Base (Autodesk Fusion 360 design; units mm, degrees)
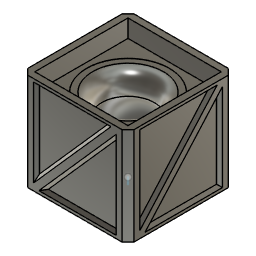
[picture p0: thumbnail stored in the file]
base_feature "Base Feature"
sketch "Sketch1" plane through (0, 0, 16.5) normal (0, 0, 1) x axis (-1, 0, 0)
  line L1 (-9, -9) -> (9, -9)
  line L2 (-9, 9) -> (-9, -9)
  line L3 (9, 9) -> (-9, 9)
  line L4 (9, -9) -> (9, 9)
  line L5 (-7, -7) -> (7, -7)
  line L6 (-7, 7) -> (-7, -7)
  line L7 (7, 7) -> (-7, 7)
  line L8 (7, -7) -> (7, 7)
  circle C1 centre (0, 0) radius 9
  circle C2 centre (0, 0) radius 7
  circle C3 centre (0, 0) radius 9
  horizontal L1
  vertical L2
  horizontal L3
  vertical L4
  horizontal L5
  vertical L6
  horizontal L7
  vertical L8
  concentric C1 C3
  tangent L1 C3
sketch "Sketch2" plane through (-9, 0, 0) normal (-1, 0, 0) x axis (0, -1, 0)
  line L1 (-9, 16.5) -> (9, 16.5)
  line L2 (-9, 0) -> (-9, 16.5)
  line L3 (9, 0) -> (-9, 0)
  line L4 (9, 16.5) -> (9, 0)
  line L5 (6.5, 1) -> (-6.5, 1)
  line L6 (-6.5, 15.5) -> (6.5, 15.5)
  line L7 (-6.5, 1) -> (-6.5, 15.5)
  line L8 (6.5, 15.5) -> (6.5, 1)
  line L9 (6.5, 14) -> (-5, 1)
  line L10 (-6.5, 2.5) -> (5, 15.5)
  point P8 (-6.5, 2.5)
  point P9 (-5, 1)
  point P13 (6.5, 14)
  point P7 (5, 15.5)
  horizontal L5
  vertical L8
  horizontal L6
  vertical L7
  coincident P8 L7
  coincident P9 L5
  coincident P13 L8
  coincident P7 L6
sketch "Sketch3" plane through (0, 9, 0) normal (0, 1, 0) x axis (-1, 0, 0)
  line L1 (-9, 16.5) -> (9, 16.5)
  line L2 (-9, 0) -> (-9, 16.5)
  line L3 (9, 0) -> (-9, 0)
  line L4 (9, 16.5) -> (9, 0)
  line L5 (6.5, 1) -> (-6.5, 1)
  line L6 (-6.5, 15.5) -> (6.5, 15.5)
  line L7 (-6.5, 1) -> (-6.5, 15.5)
  line L8 (6.5, 15.5) -> (6.5, 1)
  line L9 (6.5, 14) -> (-5, 1)
  line L10 (-6.5, 2.5) -> (5, 15.5)
  point P8 (-6.5, 2.5)
  point P9 (-5, 1)
  point P13 (6.5, 14)
  point P7 (5, 15.5)
  horizontal L5
  vertical L8
  horizontal L6
  vertical L7
  coincident P8 L7
  coincident P9 L5
  coincident P13 L8
  coincident P7 L6
sketch "Sketch4" plane through (0, 0, 16.5) normal (0, 0, 1) x axis (-1, 0, 0)
  line L1 (7, -7) -> (7, 7)
  line L2 (-7, -7) -> (7, -7)
  line L3 (-7, 7) -> (-7, -7)
  line L4 (7, 7) -> (-7, 7)
  line L5 (-9, 8) -> (-8, 9)
  line L6 (-9, -8) -> (-9, 8)
  line L7 (-8, -9) -> (-9, -8)
  line L8 (8, -9) -> (-8, -9)
  line L9 (9, -8) -> (8, -9)
  line L10 (9, 8) -> (9, -8)
  line L11 (8, 9) -> (9, 8)
  line L12 (-8, 9) -> (8, 9)
  line L13 (-7, -7) -> (7, -7)
  line L14 (-7, 7) -> (-7, -7)
  line L15 (7, 7) -> (-7, 7)
  line L16 (7, -7) -> (7, 7)
  line L17 (9, -8) -> (8, -9)
  line L18 (9, 8) -> (9, -8)
  line L19 (9, 8) -> (8, 9)
  line L20 (-8, 9) -> (8, 9)
  line L21 (-9, 8) -> (-8, 9)
  line L22 (-9, -8) -> (-9, 8)
  line L23 (-8, -9) -> (-9, -8)
  line L24 (8, -9) -> (-8, -9)
  line L25 (7, 5) -> (7, -5)
  line L26 (3, -5) -> (3, 5)
  line L27 (5, 5) -> (5, -5)
  line L28 (-3, 5) -> (-3, -5)
  line L29 (-7, -5) -> (-7, 5)
  line L30 (-5, 5) -> (-5, -5)
  line L31 (2, 5) -> (2, -5)
  line L32 (-2, -5) -> (-2, 5)
  line L33 (0, 5) -> (0, -5)
  line L34 (-5, 2) -> (5, 2)
  line L35 (5, -2) -> (-5, -2)
  line L36 (-5, 0) -> (5, 0)
  line L37 (-7.9, -7.9) -> (7.9, -7.9)
  line L38 (-7.9, 7.9) -> (-7.9, -7.9)
  line L39 (7.9, 7.9) -> (-7.9, 7.9)
  line L40 (7.9, -7.9) -> (7.9, 7.9)
  arc A1 centre (5, 5) radius 2 clockwise from (3, 5) to (7, 5)
  arc A2 centre (5, -5) radius 2 clockwise from (7, -5) to (3, -5)
  arc A3 centre (-5, 5) radius 2 clockwise from (-7, 5) to (-3, 5)
  arc A4 centre (-5, -5) radius 2 clockwise from (-3, -5) to (-7, -5)
  arc A5 centre (0, 5) radius 2 clockwise from (-2, 5) to (2, 5)
  arc A6 centre (0, -5) radius 2 clockwise from (2, -5) to (-2, -5)
  arc A7 centre (-5, 0) radius 2 clockwise from (-5, -2) to (-5, 2)
  arc A8 centre (5, 0) radius 2 clockwise from (5, 2) to (5, -2)
  point P5 (-7, 7)
  point P16 (-7, 7)
  point P3 (7, -7)
  point P14 (7, -7)
  point P10 (8, -9)
  point P18 (8, -9)
  point P11 (9, -8)
  point P19 (9, -8)
  point P12 (9, 8)
  point P20 (9, 8)
  point P13 (8, 9)
  point P21 (8, 9)
  point P6 (-8, 9)
  point P22 (-8, 9)
  point P7 (-9, 8)
  point P23 (-9, 8)
  point P8 (-9, -8)
  point P24 (-9, -8)
  point P25 (-9, -8)
  point P9 (-8, -9)
  point P26 (-8, -9)
  point P50 (-5, 0)
  point P1 (0, 0)
  point P51 (0, 0)
  horizontal L13
  vertical L14
  horizontal L15
  vertical L16
  coincident P5 P16
  coincident P3 P14
  coincident P10 P18
  coincident P11 P19
  coincident P12 P20
  coincident P13 P21
  coincident P6 P22
  coincident P7 P23
  coincident P8 P24
  coincident P8 P25
  coincident P9 P26
  tangent L25 A1
  tangent A1 L26
  parallel L25 L26
  tangent L26 A2
  tangent L25 A2
  perpendicular L13 L27
  tangent L28 A3
  tangent A3 L29
  parallel L28 L29
  tangent L29 A4
  tangent L28 A4
  perpendicular L13 L30
  tangent L31 A5
  tangent A5 L32
  parallel L31 L32
  tangent L32 A6
  tangent L31 A6
  parallel L28 L33
  tangent L34 A7
  tangent A7 L35
  parallel L34 L35
  tangent L35 A8
  tangent L34 A8
  midpoint L30 P50
  perpendicular L30 L36
  coincident P1 P51
  midpoint L36 P51
  horizontal L37
  vertical L38
  horizontal L39
  vertical L40
  dimension "d1" distance L15 L39 = 0.9
  dimension "d3" distance L29 L38 = 0.9
  dimension "d4" distance L16 L40 = 0.9
  dimension "d5" distance L13 L37 = 0.9
sketch "Sketch5" plane through (0, -9, 0) normal (0, -1, 0) x axis (1, 0, 0)
  line L1 (-9, 16.5) -> (9, 16.5)
  line L2 (-9, 0) -> (-9, 16.5)
  line L3 (9, 0) -> (-9, 0)
  line L4 (9, 16.5) -> (9, 0)
  line L5 (6.5, 1) -> (-6.5, 1)
  line L6 (6.5, 15.5) -> (6.5, 1)
  line L7 (-6.5, 15.5) -> (6.5, 15.5)
  line L8 (-6.5, 1) -> (-6.5, 15.5)
  line L9 (6.5, 14) -> (-5, 1)
  line L10 (-6.5, 2.5) -> (5, 15.5)
  point P10 (-6.5, 2.5)
  point P11 (-5, 1)
  point P12 (6.5, 14)
  point P13 (5, 15.5)
  horizontal L5
  vertical L6
  horizontal L7
  vertical L8
  coincident L8 P10
  coincident L5 P11
  coincident L6 P12
  coincident L7 P13
sketch "Sketch6" plane through (0, 0, 0) normal (0, 1, 0) x axis (1, 0, 0)
  line L1 (0, -1.0393) -> (0, 0)
  line L2 (0, -6.5393) -> (0, -1.0393)
  line L3 (7, -13.5223) -> (6, -13.5223)
  line L4 (7, -16.5) -> (7, -13.5223)
  line L5 (9, -16.5) -> (7, -16.5)
  line L6 (9, 0) -> (9, -16.5)
  line L7 (0, 0) -> (9, 0)
  line L8 (1.5, -23.3515) -> (1.5, -13.3515)
  line L9 (3, -2.5393) -> (0, -2.5393)
  line L10 (2.4121, -24.2636) -> (1.5, -23.3515)
  line L11 (2.4121, -27) -> (2.4121, -24.2636)
  line L12 (0, -27) -> (2.4121, -27)
  line L13 (0, 0) -> (0, -27)
  arc A1 centre (0, -6.5393) radius 5.5 clockwise from (0, -1.0393) to (4.4732, -9.7394)
  arc A2 centre (6.6757, -11.05) radius 2.5629 clockwise from (6, -13.5223) to (4.4732, -9.7394)
  arc A3 centre (4.8794, -13.3515) radius 3.3794 clockwise from (1.5, -13.3515) to (2.9115, -10.6041)
  arc A4 centre (0, -6.5393) radius 5 clockwise from (3, -2.5393) to (2.9115, -10.6041)
  point P1 (0, 0)
  point P2 (0, 0)
  point P4 (0, -6.5393)
  point P5 (0, -6.5393)
  point P13 (0, 0)
  point P18 (0, -2.5393)
  point P24 (0, 0)
  point P3 (0, -1.0393)
  point P19 (3, -2.5393)
  point P15 (1.5, -13.3515)
  point P17 (1.5, -23.3515)
  point P8 (6, -13.5223)
  point P9 (7, -13.5223)
  coincident P1 P2
  vertical L1
  parallel L1 L2
  coincident P4 P5
  horizontal L3
  perpendicular L3 L4
  perpendicular L4 L5
  perpendicular L5 L6
  coincident P1 P13
  perpendicular L1 L7
  tangent A3 L8
  coincident L2 P18
  parallel L8 L11
  perpendicular L11 L12
  coincident P1 P24
  perpendicular L7 L13
  tangent A3 A4
  dimension "d6" distance P3 P4 = 5.5
  dimension "d7" distance P18 P19 = 3
  dimension "d8" distance P15 P17 = 10
  dimension "d9" distance L8 L13 = 1.5
  dimension "d10" distance P8 P9 = 1
sketch "Sketch7" plane through (9, 0, 0) normal (1, 0, 0) x axis (0, 1, 0)
  line L1 (-9, 16.5) -> (9, 16.5)
  line L2 (-9, 0) -> (-9, 16.5)
  line L3 (9, 0) -> (-9, 0)
  line L4 (9, 16.5) -> (9, 0)
  line L5 (6.5, 1) -> (-6.5, 1)
  line L6 (-6.5, 15.5) -> (6.5, 15.5)
  line L7 (-6.5, 1) -> (-6.5, 15.5)
  line L8 (6.5, 15.5) -> (6.5, 1)
  line L9 (6.5, 14) -> (-5, 1)
  line L10 (-6.5, 2.5) -> (5, 15.5)
  point P8 (-6.5, 2.5)
  point P9 (-5, 1)
  point P13 (6.5, 14)
  point P7 (5, 15.5)
  horizontal L5
  vertical L8
  horizontal L6
  vertical L7
  coincident P8 L7
  coincident P9 L5
  coincident P13 L8
  coincident P7 L6
revolve "Revolve1" sketch "Sketch6" AlongAngle 360
extrude "Extrude4" add sketch "Sketch1" profile of C1 L1 L2 L3 L4 L5 L6 L7 L8 C3 against normal blind 16.5
extrude "Extrude5" cut sketch "Sketch1" profile of C1 C2 L5 L6 L7 L8 C3 against normal blind 3
extrude "Extrude6" cut sketch "Sketch5" profile of L5 L6 L7 L8 L9 L10 against normal blind 0.5
extrude "Extrude7" cut sketch "Sketch2" profile of L5 L6 L7 L8 L9 L10 against normal blind 0.5
extrude "Extrude8" cut sketch "Sketch3" profile of L5 L6 L7 L8 L9 L10 against normal blind 0.5
extrude "Extrude9" cut sketch "Sketch7" profile of L5 L6 L7 L8 L9 L10 against normal blind 0.5
chamfer "Chamfer1" distance 0.5
chamfer "Chamfer2" distance 1
extrude "Extrude10" cut sketch "Sketch4" profile of L1 L2 L3 L4 L13 L14 L15 L16 L25 L29 L37 L38 L39 L40 against normal blind 3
